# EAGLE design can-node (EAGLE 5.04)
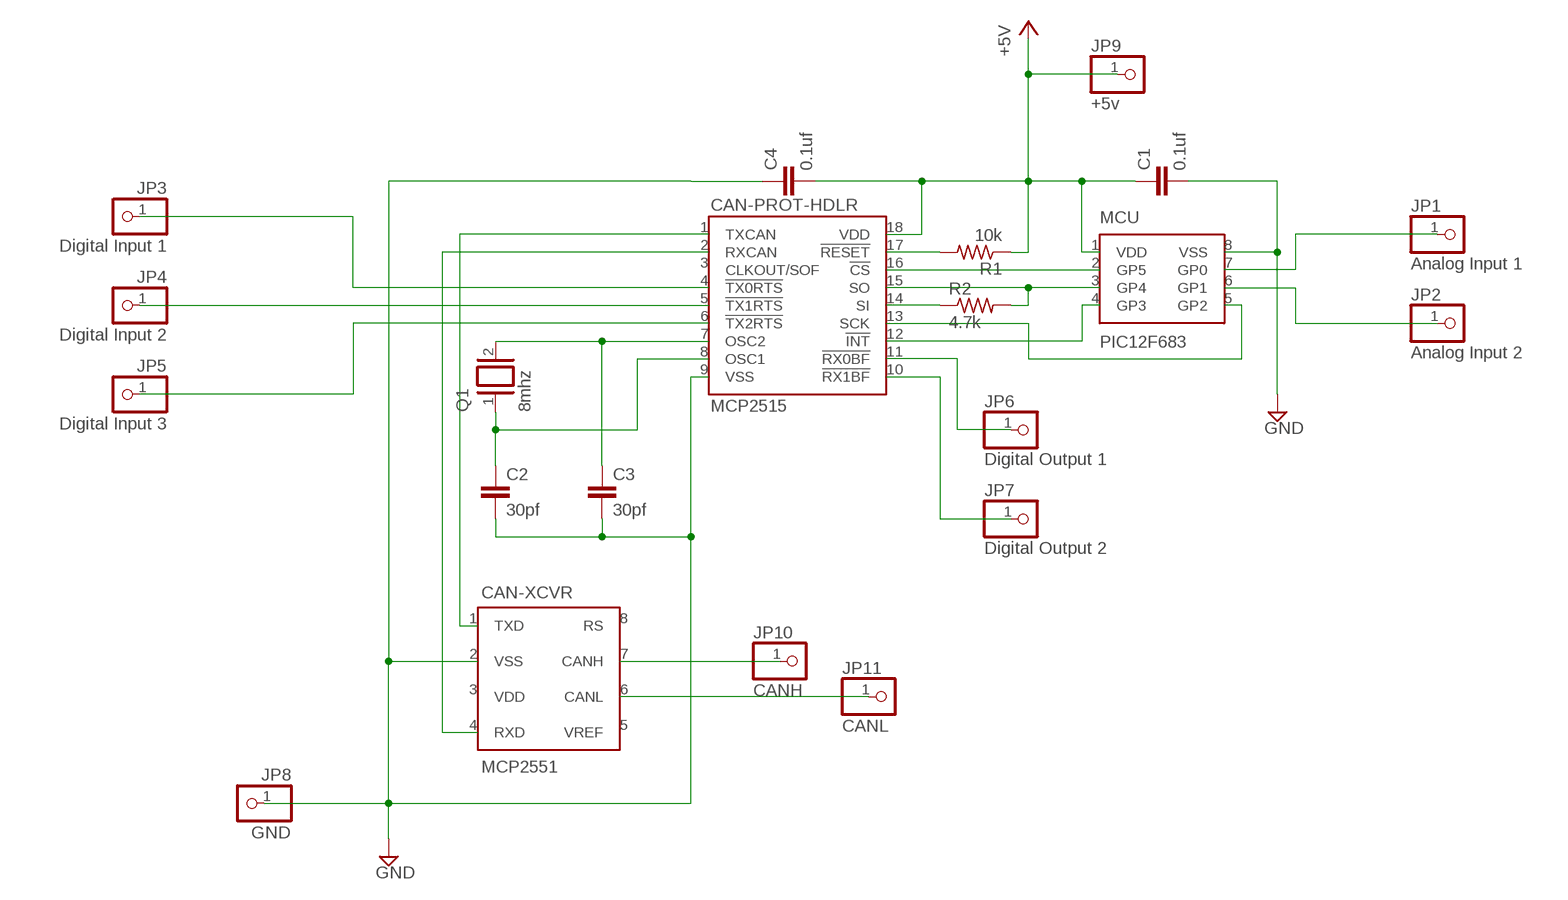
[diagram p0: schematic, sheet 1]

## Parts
C1  0.1uf  C-EU050-024X044  [C050-024X044]
C2  30pf  C-EU050-024X044  [C050-024X044]
C3  30pf  C-EU050-024X044  [C050-024X044]
C4  0.1uf  C-EU050-024X044  [C050-024X044]
CAN-PROT-HDLR  MCP2515  [DIL18-3]
CAN-XCVR  MCP2551  [DIL8-3]
JP1  Analog Input 1  PINHD-1X1  [1X01]
JP2  Analog Input 2  PINHD-1X1  [1X01]
JP3  Digital Input 1  PINHD-1X1  [1X01]
JP4  Digital Input 2  PINHD-1X1  [1X01]
JP5  Digital Input 3  PINHD-1X1  [1X01]
JP6  Digital Output 1  PINHD-1X1  [1X01]
JP7  Digital Output 2  PINHD-1X1  [1X01]
JP8  GND  PINHD-1X1  [1X01]
JP9  +5v  PINHD-1X1  [1X01]
JP10  CANH  PINHD-1X1  [1X01]
JP11  CANL  PINHD-1X1  [1X01]
MCU  PIC12F683  [DIL8-3]
Q1  8mhz  XTAL/S  [QS]
R1  10k  R-US_0207/7  [0207/7]
R2  4.7k  R-US_0207/7  [0207/7]

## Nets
+5V: C1.1 C4.2 CAN-PROT-HDLR.18(VDD) JP9.1 MCU.1(VDD) R1.1
GND: C1.2 C2.2 C3.2 C4.1 CAN-PROT-HDLR.9(VSS) CAN-XCVR.2(VSS) JP8.1 MCU.8(VSS)
N$1: C2.1 CAN-PROT-HDLR.8(OSC1) Q1.1
N$2: C3.1 CAN-PROT-HDLR.7(OSC2) Q1.2
N$3: CAN-PROT-HDLR.4(!TX0RTS) JP3.1
N$4: CAN-PROT-HDLR.1(TXCAN) CAN-XCVR.1(TXD)
N$5: CAN-PROT-HDLR.2(RXCAN) CAN-XCVR.4(RXD)
N$6: CAN-XCVR.7(CANH) JP10.1
N$7: CAN-XCVR.6(CANL) JP11.1
N$8: CAN-PROT-HDLR.5(!TX1RTS) JP4.1
N$9: CAN-PROT-HDLR.6(!TX2RTS) JP5.1
N$10: CAN-PROT-HDLR.17(!RESET) R1.2
N$11: CAN-PROT-HDLR.14(SI) R2.1
N$12: JP1.1 MCU.7(GP0)
N$13: CAN-PROT-HDLR.16(!CS) MCU.2(GP5)
N$14: CAN-PROT-HDLR.15(SO) MCU.3(GP4) R2.2
N$15: CAN-PROT-HDLR.12(!INT) MCU.4(GP3)
N$16: CAN-PROT-HDLR.13(SCK) MCU.5(GP2)
N$17: JP2.1 MCU.6(GP1)
N$18: CAN-PROT-HDLR.11(!RX0BF) JP6.1
N$19: CAN-PROT-HDLR.10(!RX1BF) JP7.1
Unconnected: CAN-PROT-HDLR.3(CLKOUT/SOF) CAN-XCVR.3(VDD) CAN-XCVR.5(VREF) CAN-XCVR.8(RS)

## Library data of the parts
C1-C4 = rcl:C-EU: CAPACITOR, European symbol
CAN-PROT-HDLR = trl:MCP2515
CAN-XCVR = trl:MCP2551
JP1-JP11 = pinhead:PINHD-1X1: PIN HEADER
MCU = trl:PIC12F683
Q1 = special:XTAL/S: CRYSTAL
R1 R2 = resistor:R-US_: RESISTOR, American symbol

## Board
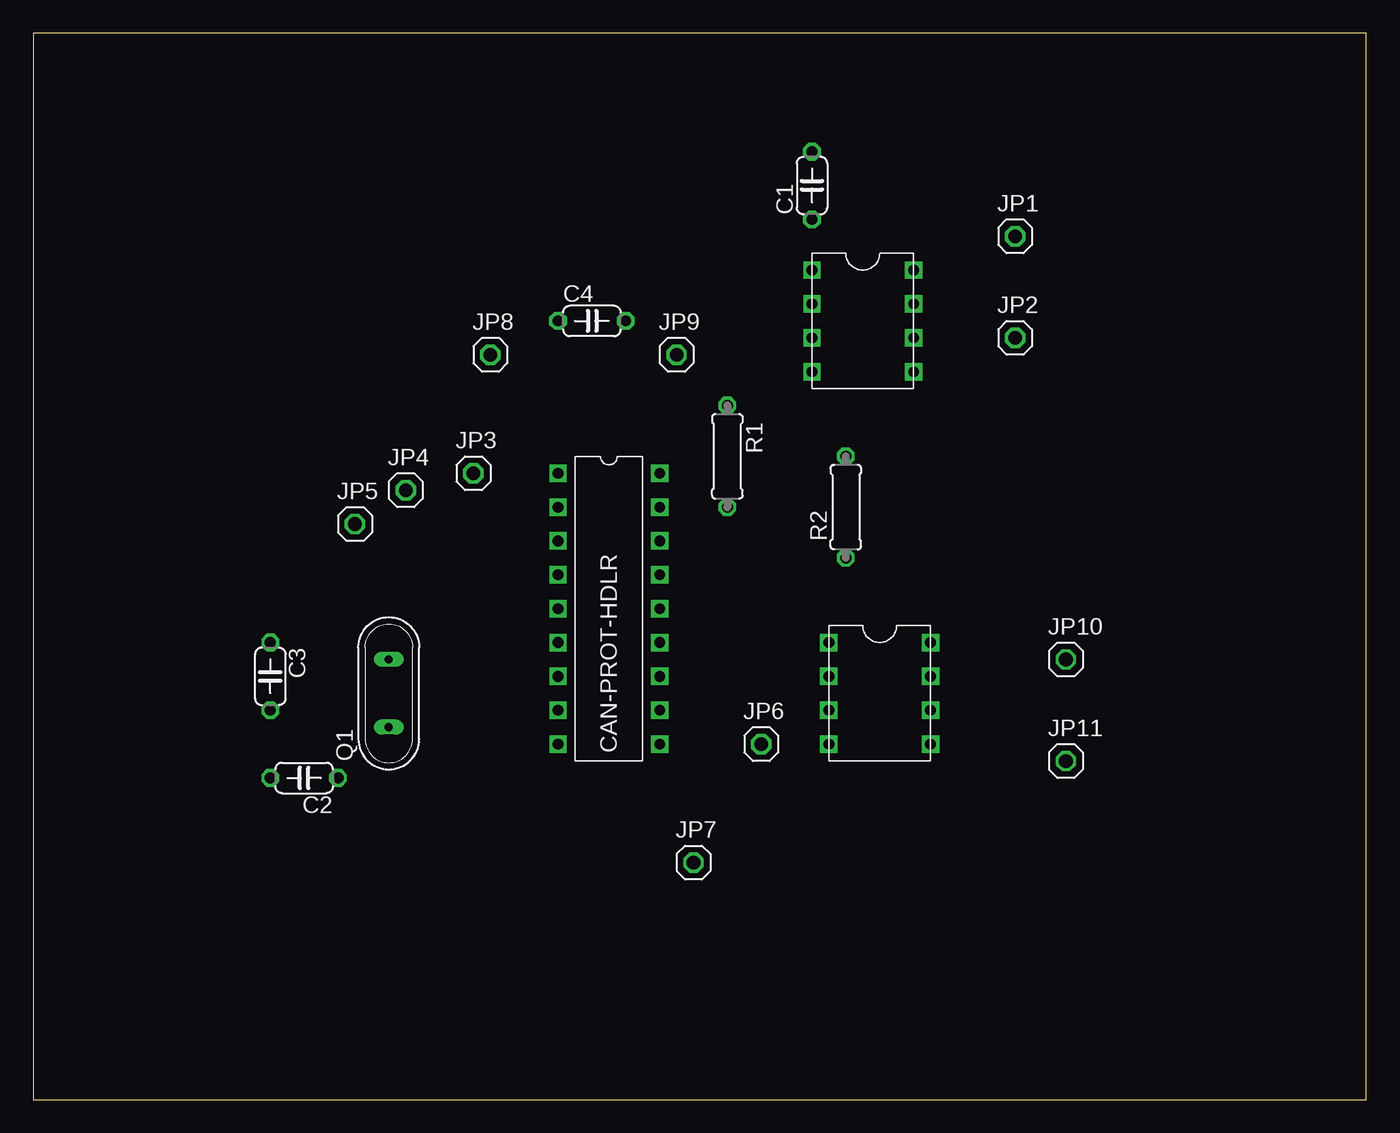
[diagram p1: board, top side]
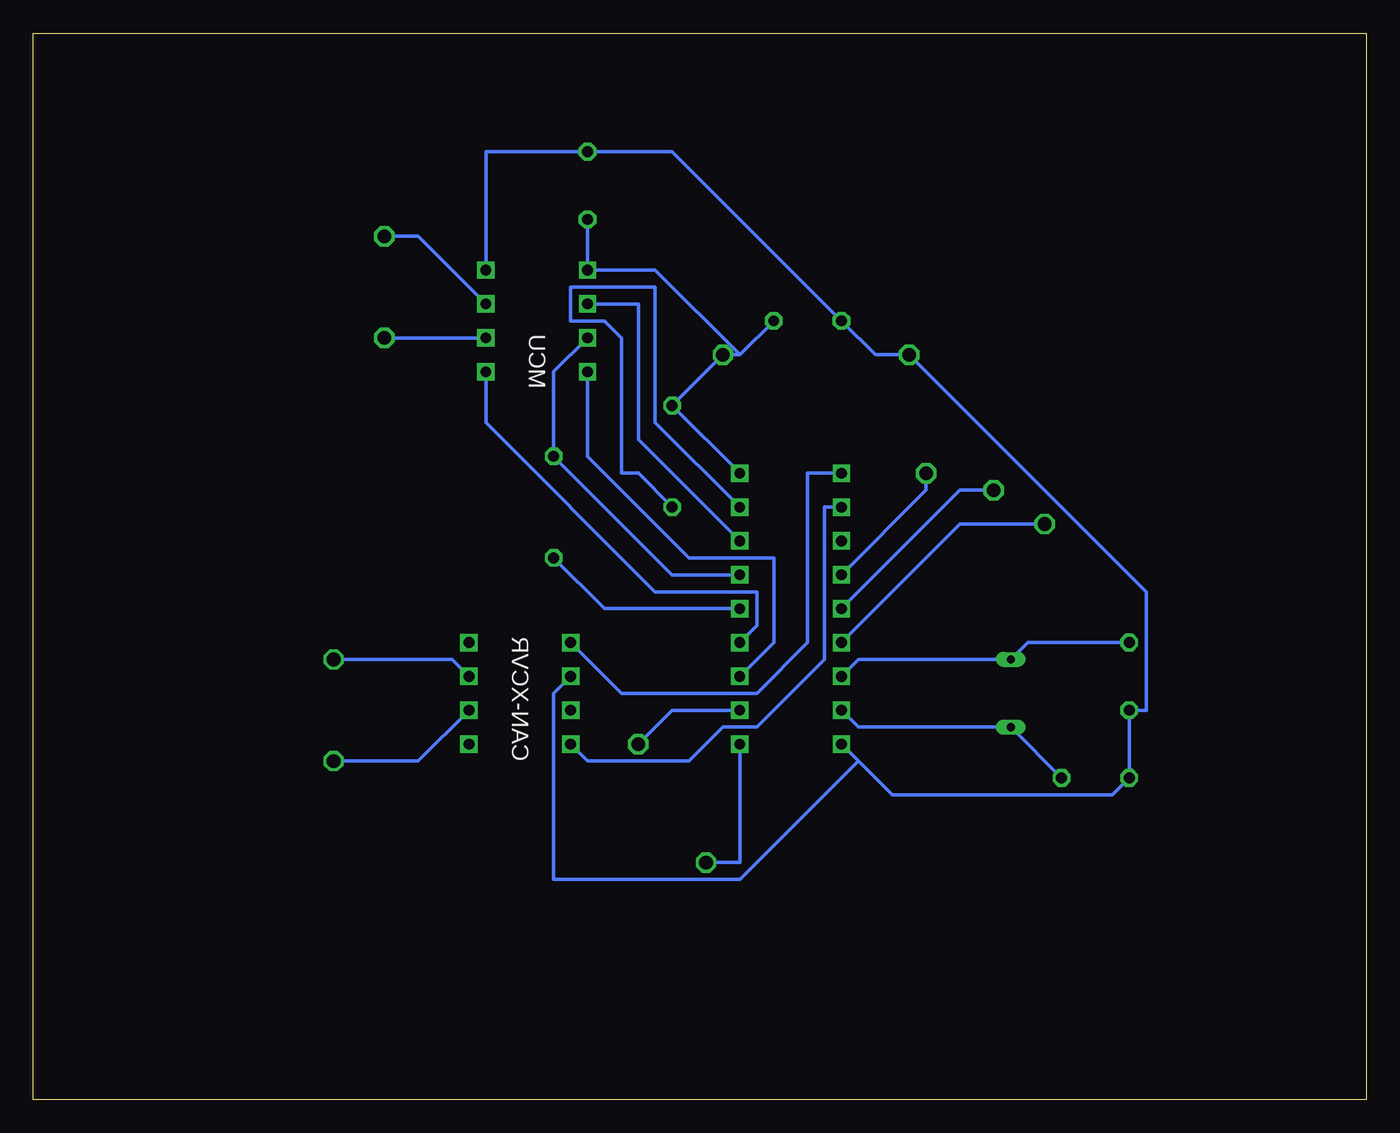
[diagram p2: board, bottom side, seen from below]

Size 100 x 80 mm. Coordinates in mm from the lower left corner, seen from the top.
Outline: 0,0 100,0 100,80 0,80 0,0
Copper layers (1*16): Top 0.035mm / dielectric 1.5mm / Bottom 0.035mm
Design rules "default": minimum track width 10mil, minimum drill 24mil, track to track 8mil, track to pad 8mil, pad to pad 8mil, via to via 8mil, smd to smd 8mil, copper to edge 40mil, drill to drill 8mil, minimum pad ring 10mil, minimum via ring 8mil, stop-mask expansion 4mil, vias tented up to drill 0mil, thermal gap 10mil

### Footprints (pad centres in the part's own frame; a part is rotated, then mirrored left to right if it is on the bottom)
C050-024X044 = drill 0.813 octagon: 1 -2.54,0; 2 2.54,0
DIL18-3 = drill 0.8 square: 1 -3.81,10.16; 2 -3.81,7.62; 3 -3.81,5.08; 4 -3.81,2.54; 5 -3.81,0; 6 -3.81,-2.54; 7 -3.81,-5.08; 8 -3.81,-7.62; 9 -3.81,-10.16; 10 3.81,-10.16; 11 3.81,-7.62; 12 3.81,-5.08; 13 3.81,-2.54; 14 3.81,0; 15 3.81,2.54; 16 3.81,5.08; 17 3.81,7.62; 18 3.81,10.16
DIL8-3 = drill 0.8 square: 1 -3.81,3.81; 2 -3.81,1.27; 3 -3.81,-1.27; 4 -3.81,-3.81; 5 3.81,-3.81; 6 3.81,-1.27; 7 3.81,1.27; 8 3.81,3.81
1X01 = drill 1.016 octagon: 1 0,0
QS = drill 0.61 long: 1 -2.54,0; 2 2.54,0
0207/7 = drill 0.813 octagon: 1 -3.81,0; 2 3.81,0

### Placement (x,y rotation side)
C1  58.42,68.58 90 top
C2  20.32,24.13 180 top
C3  17.78,31.75 270 top
C4  41.91,58.42 0 top
CAN-PROT-HDLR  43.18,36.83 0 top
CAN-XCVR  63.5,30.48 0 top
JP1  73.66,64.77 0 top
JP2  73.66,57.15 0 top
JP3  33.02,46.99 0 top
JP4  27.94,45.72 0 top
JP5  24.13,43.18 0 top
JP6  54.61,26.67 0 top
JP7  49.53,17.78 0 top
JP8  34.29,55.88 0 top
JP9  48.26,55.88 0 top
JP10  77.47,33.02 0 top
JP11  77.47,25.4 0 top
MCU  62.23,58.42 0 top
Q1  26.67,30.48 90 top
R1  52.07,48.26 270 top
R2  60.96,44.45 90 top

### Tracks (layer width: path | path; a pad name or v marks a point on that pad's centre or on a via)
+5V
  Bottom 0.254: CAN-PROT-HDLR.18 R1.1 JP9.1 46.99,55.88 | C1.1 MCU.1 53.34,62.23 46.99,55.88 | 46.99,55.88 C4.2
GND
  Bottom 0.254: MCU.8 66.04,71.12 C1.2 52.07,71.12 C4.1 36.83,55.88 JP8.1 16.51,38.1 16.51,29.21 C3.2 C2.2 19.05,22.86 35.56,22.86 38.1,25.4 | 38.1,25.4 CAN-PROT-HDLR.9 | CAN-XCVR.2 60.96,30.48 60.96,16.51 46.99,16.51 38.1,25.4
N$1
  Bottom 0.254: C2.1 Q1.1 38.1,27.94 CAN-PROT-HDLR.8
N$2
  Bottom 0.254: C3.1 25.4,34.29 Q1.2 38.1,33.02 CAN-PROT-HDLR.7
N$3
  Bottom 0.254: CAN-PROT-HDLR.4 33.02,45.72 JP3.1
N$4
  Bottom 0.254: CAN-XCVR.1 55.88,30.48 45.72,30.48 41.91,34.29 41.91,46.99 CAN-PROT-HDLR.1
N$5
  Bottom 0.254: CAN-XCVR.4 58.42,25.4 50.8,25.4 48.26,27.94 45.72,27.94 40.64,33.02 40.64,44.45 CAN-PROT-HDLR.2
N$6
  Bottom 0.254: CAN-XCVR.7 68.58,33.02 JP10.1
N$7
  Bottom 0.254: CAN-XCVR.6 71.12,25.4 JP11.1
N$8
  Bottom 0.254: CAN-PROT-HDLR.5 30.48,45.72 JP4.1
N$9
  Bottom 0.254: CAN-PROT-HDLR.6 30.48,43.18 JP5.1
N$10
  Bottom 0.254: CAN-PROT-HDLR.17 53.34,50.8 53.34,60.96 59.69,60.96 59.69,58.42 57.15,58.42 55.88,57.15 55.88,46.99 54.61,46.99 R1.2
N$11
  Bottom 0.254: CAN-PROT-HDLR.14 57.15,36.83 R2.1
N$12
  Bottom 0.254: MCU.7 71.12,64.77 JP1.1
N$13
  Bottom 0.254: CAN-PROT-HDLR.16 54.61,49.53 54.61,59.69 MCU.2
N$14
  Bottom 0.254: CAN-PROT-HDLR.15 52.07,39.37 R2.2 60.96,54.61 MCU.3
N$15
  Bottom 0.254: CAN-PROT-HDLR.12 44.45,34.29 44.45,40.64 50.8,40.64 58.42,48.26 MCU.4
N$16
  Bottom 0.254: CAN-PROT-HDLR.13 45.72,35.56 45.72,38.1 53.34,38.1 66.04,50.8 MCU.5
N$17
  Bottom 0.254: MCU.6 JP2.1
N$18
  Bottom 0.254: CAN-PROT-HDLR.11 52.07,29.21 JP6.1
N$19
  Bottom 0.254: CAN-PROT-HDLR.10 46.99,17.78 JP7.1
